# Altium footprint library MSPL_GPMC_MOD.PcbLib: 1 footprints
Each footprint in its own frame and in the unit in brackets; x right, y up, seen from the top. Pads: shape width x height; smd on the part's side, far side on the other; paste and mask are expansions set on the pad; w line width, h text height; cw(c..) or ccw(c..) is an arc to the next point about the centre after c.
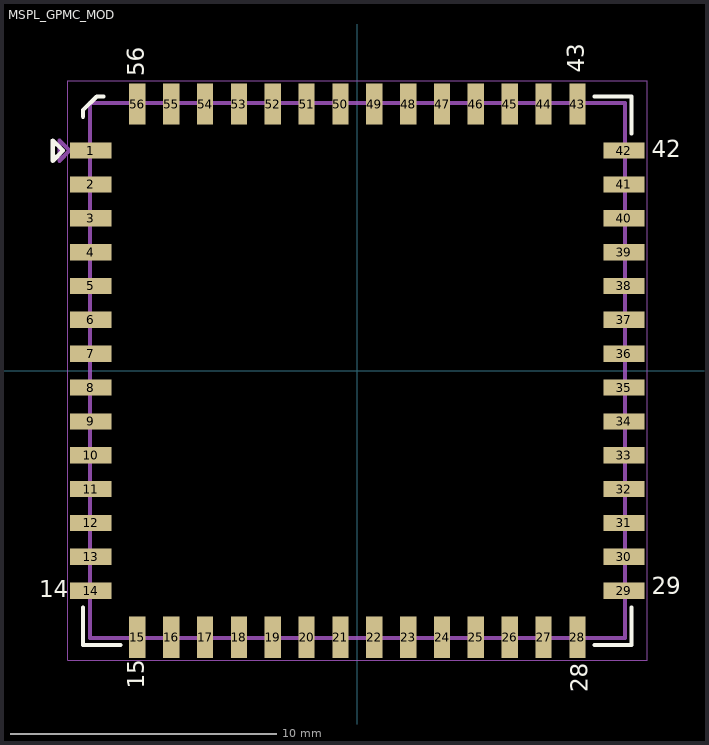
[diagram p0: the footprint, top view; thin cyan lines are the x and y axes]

## MSPL_GPMC_MOD [mil]
height 59
pads (56):
  rect 61x24 smd mask+3: 1(-393.7,325) 2(-393.7,275) 3(-393.7,225) 4(-393.7,175) 5(-393.7,125) 6(-393.7,75) 7(-393.7,25) 8(-393.7,-25) 9(-393.7,-75) 10(-393.7,-125) 11(-393.7,-175) 12(-393.7,-225) 13(-393.7,-275) 14(-393.7,-325) 29(393.7,-325) 30(393.7,-275) 31(393.7,-225) 32(393.7,-175) 33(393.7,-125) 34(393.7,-75) 35(393.7,-25) 36(393.7,25) 37(393.7,75) 38(393.7,125) 39(393.7,175) 40(393.7,225) 41(393.7,275) 42(393.7,325)
  rect 24x61 smd mask+3: 15(-325,-393.7) 16(-275,-393.7) 17(-225,-393.7) 18(-175,-393.7) 19(-125,-393.7) 20(-75,-393.7) 21(-25,-393.7) 22(25,-393.7) 23(75,-393.7) 24(125,-393.7) 25(175,-393.7) 26(225,-393.7) 27(275,-393.7) 28(325,-393.7) 43(325,393.7) 44(275,393.7) 45(225,393.7) 46(175,393.7) 47(125,393.7) 48(75,393.7) 49(25,393.7) 50(-25,393.7) 51(-75,393.7) 52(-125,393.7) 53(-175,393.7) 54(-225,393.7) 55(-275,393.7) 56(-325,393.7)
Top Overlay:
  lines w6: -405,-350 -405,-405 -350,-405 ; -405,375 -405,385 -385,405 -375,405 ; 350,-405 405,-405 405,-350 ; 350,405 405,405 405,350 ; -450,310 -450,340 -435,325 -450,310
  text "56" at -315,435 h25
  text "43" at 335,440 h25
  text "42" at 435,315 h25
  text "29" at 435,-330 h25
  text "28" at 340,-475 h25
  text "15" at -315,-470 h25
  text "14" at -470,-335 h25
ASSEMBLY TOP:
  lines w6: -440,310 -440,340 -425,325 -440,310 ; -395,-395 -395,395 395,395 395,-395 -395,-395
  text ".designator" at -95,-10 h25
DFA TOP:
  region: 20,-445
  lines w1: -428.2,-428.2 -428.2,428.2 428.2,428.2 428.2,-428.2 -428.2,-428.2
3D body: height 59.06, standoff 0, extent -395,-395 395,395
